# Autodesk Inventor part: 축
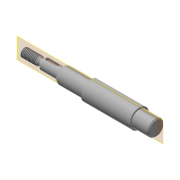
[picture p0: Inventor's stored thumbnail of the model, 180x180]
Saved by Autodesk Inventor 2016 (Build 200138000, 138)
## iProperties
Created: 2015-11
Part Number: 축
Material: 강철, 연강
Document SubType Name: Modeling
Designer: mduedu
Density: 1 g/cm^3
Appearance: 강철
Author: mduedu
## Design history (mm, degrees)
sketch "스케치1"
  geometry: L1 (-86, 0)-(86, 0); L2 (-86, 0)-(-86, 4); L3 (-86, 4)-(-70.732, 4); L4 (-70.732, 4)-(-69, 3); L5 (-69, 3)-(-67, 3); L6 (-67, 3)-(-67, 5); L7 (-67, 5)-(-49, 5); L8 (-49, 5)-(-49, 6.55); L9 (-47.355, 7.5)-(-23, 7.5); L10 (-23, 7.5)-(-23, 9); L11 (0, 0)-(0, 9); L12 (86, 4)-(70.732, 4); L13 (70.732, 4)-(69, 3); L14 (69, 3)-(67, 3); L15 (67, 3)-(67, 5); L16 (67, 5)-(49, 5); L17 (23, 7.5)-(23, 9); L18 (86, 0)-(86, 4); L19 (-23, 9)-(23, 9); L20 (-49, 6.55)-(-47.355, 7.5); L21 (47.355, 7.5)-(23, 7.5); L22 (49, 6.55)-(47.355, 7.5); L23 (49, 5)-(49, 6.55); 1 further point
  constraints: 46 end point, 10 symmetric about line, 6 perpendicular, 5 parallel, 2 midpoint, 1 coincident, 1 horizontal
  dimensions: "d0" = 172 distance of L1.start L1.end (derived); "d1" = 8 diameter of L3 L1; "d2" = 30 deg angle of L4 L5; "d3" = 6 diameter of L5 L1; "d4" = 10 diameter of L7 L1; "d5" = 15 diameter of L9 L1; "d6" = 18 diameter of L19 L1; "d8" = 18 distance of L6.end L7.end; "d9" = 46 distance of L10.end L17.end; "d10" = 2 distance of L4.end L5.end; "d11" = 17 distance from line of L4.end L2; "d16" = 13.1 diameter of L8.end L1; "d17" = 30 deg angle of L20 L9; "d18" = 26 distance between parallel lines of L10 L8
revolve "회전1" sketch "스케치1" stored, may be unused: angle "d12" = 90 deg
chamfer "모따기1" distance "d13" = 1; stored, may be unused: second distance "d14" = 2, angle "d15" = 45 deg
fillet "모깎기1" dims "d19" = 4, "d20" = 0.5
node "작업 평면1"
sketch "스케치2" dims "d23" = 12
  geometry: L1 (-5.5, 1.5)-(3.5, 1.5); L2 (3.5, 1.5)-(3.5, -1.5); L3 (3.5, -1.5)-(-5.5, -1.5); L4 (-5.5, -1.5)-(-5.5, 1.5); L5 (-9, -4)-(-9, 4) reference; 3 further points
  constraints: 8 end point, 2 midpoint, 2 parallel, 2 vertical alignment, 1 horizontal, 1 perpendicular, 4 other
  dimensions: "d21" = 3 distance between parallel lines of L3 L1; "d24" = 2 dimension on L5
extrude "돌출1" cut sketch "스케치2" distance "d25" = 1.8; taper "d26" = 0 deg
feature "스레드1" dims "d27" = 10, "d28" = 0
feature "스레드2" dims "d29" = 10, "d30" = 0
chamfer "모따기2" distance "d31" = 1; stored, may be unused: second distance "d32" = 2, angle "d33" = 45 deg
node "작업 평면2"
sketch "스케치3"
  geometry: C1 r 7.5 at (0, 0) reference; 1 further point
extrude "돌출2" cut sketch "스케치3" stored distance "d36" = 10; taper "d37" = 0 deg
chamfer "모따기3" distance "d38" = 1; stored, may be unused: second distance "d39" = 2, angle "d40" = 45 deg
node "작업 평면3"
node "솔리드1"
mirror "대칭1"
node "절단 모서리 투영1"
other parameters: "d35" = 16
